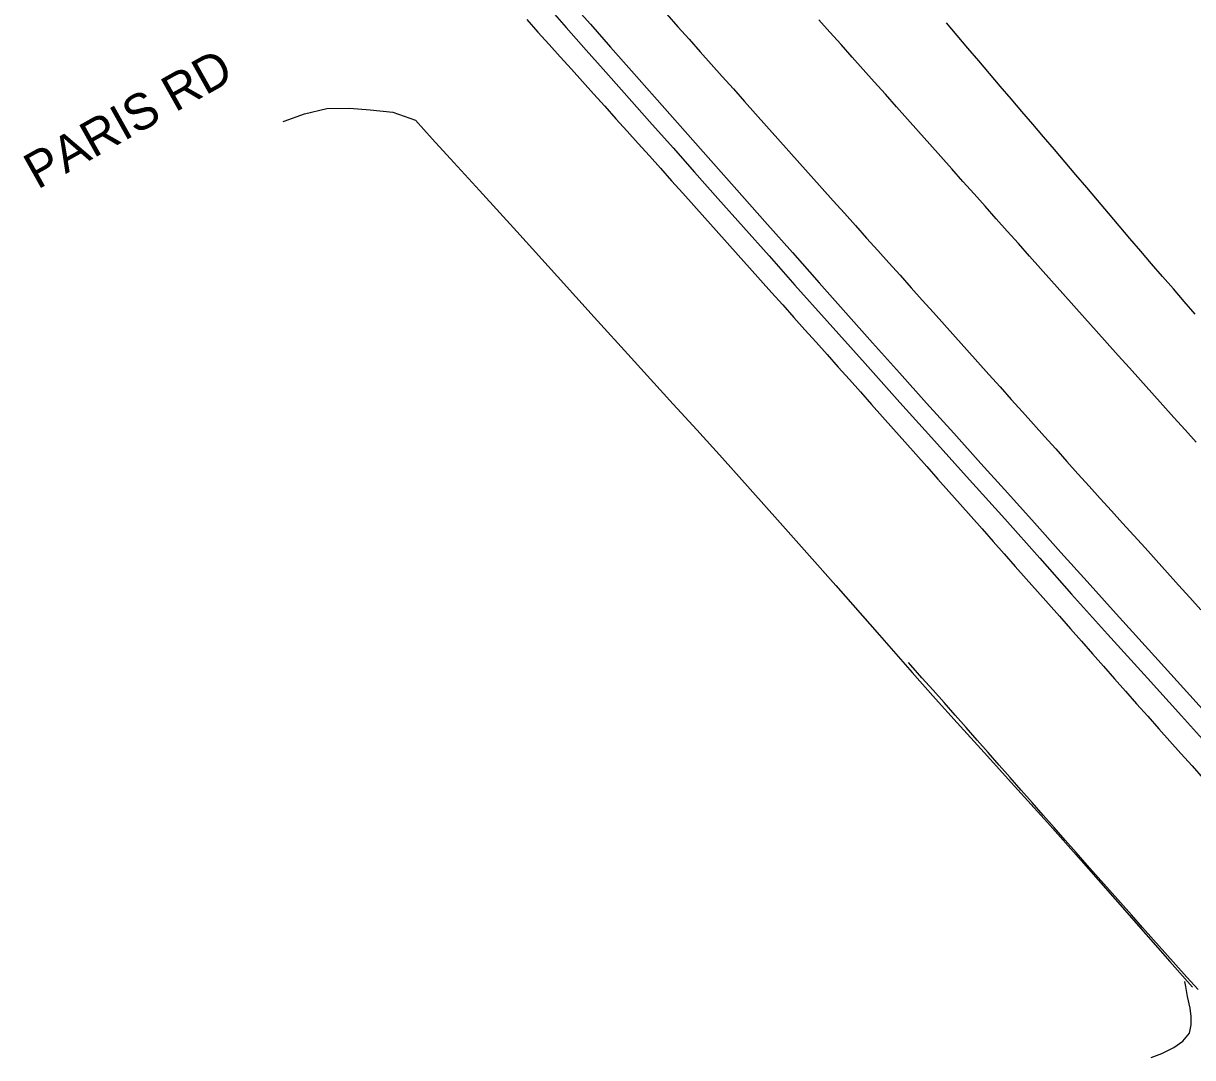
# Model space of a CAD drawing. Extents: x 1948091 to 1975253, y 787267 to 823306.
# Drawn here: x 1957756.5 to 1957931.9, y 811469.6 to 811624.7 of the extents above; entities that cross this region are included whole.
import ezdxf

# ---------------------------------------------------------------- set-up
doc = ezdxf.new("R2010")
doc.units = 0
for name, color, linetype in [('RD_EX_Pavement_Markings', 7, 'Continuous'), ('RD_EX_Road', 7, 'Continuous'), ('RD_TX_RoadID', 7, 'Continuous')]:
    doc.layers.add(name, color=color, linetype=linetype)

msp = doc.modelspace()

# ---------------------------------------------------------------- linework, layer by layer
at = {"layer": 'RD_EX_Pavement_Markings'}
for points in [[(1957853.05, 811626.1), (1957854.71, 811624.23), (1957856.38, 811622.36), (1957858.04, 811620.49), (1957859.7, 811618.63), (1957861.36, 811616.76), (1957863.02, 811614.89), (1957864.68, 811613.02), (1957866.35, 811611.16), (1957868.01, 811609.29), (1957869.67, 811607.42), (1957871.33, 811605.56), (1957873, 811603.69), (1957874.67, 811601.83), (1957876.34, 811599.97), (1957878.01, 811598.11), (1957879.68, 811596.25), (1957881.35, 811594.39), (1957883.01, 811592.53), (1957884.68, 811590.66), (1957886.35, 811588.8), (1957888.02, 811586.94), (1957889.69, 811585.08), (1957891.36, 811583.22), (1957893.03, 811581.36), (1957894.69, 811579.5), (1957896.36, 811577.64), (1957898.03, 811575.77), (1957899.7, 811573.91), (1957901.37, 811572.05), (1957903.04, 811570.19), (1957904.71, 811568.33), (1957906.38, 811566.47), (1957908.04, 811564.61), (1957909.71, 811562.74), (1957911.38, 811560.88), (1957913.05, 811559.02), (1957914.72, 811557.16), (1957916.39, 811555.3), (1957918.07, 811553.45), (1957919.75, 811551.59), (1957921.42, 811549.74), (1957923.1, 811547.89), (1957924.78, 811546.03), (1957926.45, 811544.18), (1957928.13, 811542.32), (1957929.81, 811540.47), (1957931.49, 811538.62), (1957933.16, 811536.76)], [(1957832.05, 811625.31), (1957833.71, 811623.44), (1957835.38, 811621.58), (1957837.05, 811619.72), (1957838.72, 811617.86), (1957840.39, 811616.01), (1957842.06, 811614.15), (1957843.74, 811612.29), (1957845.41, 811610.43), (1957847.08, 811608.57), (1957848.75, 811606.71), (1957850.43, 811604.85), (1957852.09, 811602.99), (1957853.76, 811601.13), (1957855.43, 811599.27), (1957857.09, 811597.4), (1957858.76, 811595.54), (1957860.43, 811593.68), (1957862.09, 811591.81), (1957863.76, 811589.95), (1957865.43, 811588.08), (1957867.09, 811586.22), (1957868.76, 811584.36), (1957870.42, 811582.49), (1957872.09, 811580.63), (1957873.76, 811578.77), (1957875.42, 811576.9), (1957877.09, 811575.04), (1957878.75, 811573.17), (1957880.42, 811571.31), (1957882.08, 811569.44), (1957883.74, 811567.57), (1957885.4, 811565.7), (1957887.06, 811563.83), (1957888.72, 811561.97), (1957890.38, 811560.1), (1957892.04, 811558.23), (1957893.7, 811556.36), (1957895.36, 811554.49), (1957897.02, 811552.62), (1957898.68, 811550.75), (1957900.34, 811548.88), (1957902, 811547.01), (1957903.66, 811545.14), (1957905.31, 811543.27), (1957906.97, 811541.4), (1957908.63, 811539.52), (1957910.29, 811537.65), (1957911.94, 811535.78), (1957913.6, 811533.91), (1957915.25, 811532.03), (1957916.91, 811530.16), (1957918.56, 811528.28), (1957920.21, 811526.41), (1957921.87, 811524.53), (1957923.52, 811522.66), (1957925.18, 811520.79), (1957926.83, 811518.91), (1957928.5, 811517.05), (1957930.17, 811515.19), (1957931.83, 811513.33), (1957933.5, 811511.46)], [(1957932.46, 811561.89), (1957930.79, 811563.75), (1957929.12, 811565.61), (1957927.45, 811567.47), (1957925.78, 811569.33), (1957924.11, 811571.19), (1957922.44, 811573.05), (1957920.77, 811574.91), (1957919.1, 811576.77), (1957917.43, 811578.63), (1957915.75, 811580.49), (1957914.09, 811582.36), (1957912.43, 811584.22), (1957910.76, 811586.09), (1957909.1, 811587.96), (1957907.44, 811589.82), (1957905.78, 811591.69), (1957904.11, 811593.56), (1957902.45, 811595.42), (1957900.79, 811597.29), (1957899.13, 811599.16), (1957897.46, 811601.02), (1957895.8, 811602.89), (1957894.14, 811604.76), (1957892.48, 811606.62), (1957890.81, 811608.49), (1957889.15, 811610.36), (1957887.49, 811612.22), (1957885.83, 811614.09), (1957884.16, 811615.96), (1957882.5, 811617.82), (1957880.83, 811619.69), (1957879.17, 811621.55), (1957877.51, 811623.42), (1957875.84, 811625.28)], [(1957932.29, 811581.1), (1957930.66, 811582.99), (1957929.03, 811584.89), (1957927.4, 811586.78), (1957925.77, 811588.68), (1957924.14, 811590.57), (1957922.52, 811592.48), (1957920.9, 811594.38), (1957919.28, 811596.28), (1957917.66, 811598.19), (1957916.04, 811600.09), (1957914.42, 811601.99), (1957912.8, 811603.9), (1957911.18, 811605.8), (1957909.55, 811607.71), (1957907.93, 811609.61), (1957906.31, 811611.51), (1957904.69, 811613.42), (1957903.07, 811615.32), (1957901.45, 811617.22), (1957899.83, 811619.13), (1957898.21, 811621.03), (1957896.59, 811622.93), (1957894.97, 811624.84)], [(1957932.75, 811479.8), (1957931.07, 811481.65), (1957929.4, 811483.51), (1957927.73, 811485.36), (1957926.06, 811487.23), (1957924.4, 811489.1), (1957922.75, 811490.97), (1957921.09, 811492.84), (1957919.43, 811494.71), (1957917.77, 811496.58), (1957916.11, 811498.45), (1957914.46, 811500.33), (1957912.82, 811502.21), (1957911.17, 811504.09), (1957909.52, 811505.96), (1957907.87, 811507.84), (1957906.22, 811509.72), (1957904.57, 811511.6), (1957902.91, 811513.47), (1957901.26, 811515.34), (1957899.6, 811517.22), (1957897.94, 811519.09), (1957896.29, 811520.96), (1957894.63, 811522.83), (1957892.97, 811524.7), (1957891.31, 811526.57), (1957889.66, 811528.45), (1957889.3, 811528.85)]]:
    msp.add_lwpolyline(points, dxfattribs=at)
at = {"layer": 'RD_EX_Road'}
for points in [[(1957834.42, 811628.11), (1957837.92, 811624.14), (1957840.94, 811620.72), (1957843.47, 811617.87), (1957846.62, 811614.32), (1957850.42, 811610.03), (1957853.97, 811606.05), (1957857.2, 811602.42), (1957860.71, 811598.47), (1957864.55, 811594.15), (1957868.37, 811589.85), (1957872.25, 811585.47), (1957877.08, 811580.05), (1957882.77, 811573.7), (1957888.01, 811567.87), (1957892.76, 811562.6), (1957898, 811556.77), (1957903.74, 811550.38), (1957908.99, 811544.5), (1957913.77, 811539.11), (1957919.17, 811533.09), (1957925.14, 811526.51), (1957930.27, 811520.84), (1957934.29, 811516.37)], [(1957838.36, 811628.25), (1957841.58, 811624.6), (1957844.61, 811621.16), (1957847.73, 811617.62), (1957851.2, 811613.69), (1957855.03, 811609.36), (1957859.22, 811604.63), (1957863.54, 811599.77), (1957867.75, 811595.01), (1957871.87, 811590.36), (1957875.89, 811585.82), (1957879.87, 811581.33), (1957883.89, 811576.82), (1957887.93, 811572.3), (1957892.01, 811567.76), (1957896.1, 811563.23), (1957900.15, 811558.72), (1957904.18, 811554.24), (1957908.19, 811549.78), (1957912.17, 811545.35), (1957916.1, 811540.98), (1957920, 811536.66), (1957923.86, 811532.39), (1957927.68, 811528.17), (1957931.48, 811523.97), (1957935.24, 811519.8)], [(1957795.5, 811609.99), (1957795.63, 811610.05), (1957798.7, 811611.15), (1957802.05, 811611.98), (1957805.41, 811611.99), (1957808.51, 811611.74), (1957811.91, 811611.42), (1957815.34, 811610.22)], [(1957815.34, 811610.22), (1957817.81, 811607.43), (1957821.08, 811603.86), (1957824.95, 811599.68), (1957830.54, 811593.53), (1957836.66, 811586.75), (1957842.14, 811580.68), (1957847.69, 811574.54), (1957854.01, 811567.59), (1957857.52, 811563.73), (1957861.37, 811559.48), (1957865.53, 811554.84), (1957870.03, 811549.82), (1957874.45, 811544.86), (1957878.4, 811540.4), (1957884.92, 811532.97), (1957889.83, 811527.36), (1957893.36, 811523.39), (1957896.61, 811519.8), (1957900.63, 811515.36), (1957905.21, 811510.3), (1957910.13, 811504.84), (1957915.22, 811499.14), (1957920.3, 811493.35), (1957924.9, 811488.09), (1957928.52, 811483.98), (1957931.92, 811480.14)], [(1957925.68, 811469.57), (1957927.31, 811470.2), (1957929.1, 811471.1), (1957930.46, 811472.02), (1957931.44, 811473.22), (1957931.69, 811474.49), (1957931.68, 811475.75), (1957931.55, 811476.98), (1957931.13, 811478.73), (1957930.9, 811480.23), (1957930.74, 811481.01)]]:
    msp.add_lwpolyline(points, dxfattribs=at)

# ---------------------------------------------------------------- texts
at = {"layer": 'RD_TX_RoadID'}
msp.add_text('PARIS RD', height=5.4, rotation=29.298, dxfattribs=at).set_placement((1957758.63, 811599.75))

doc.saveas('drawing.dxf')
